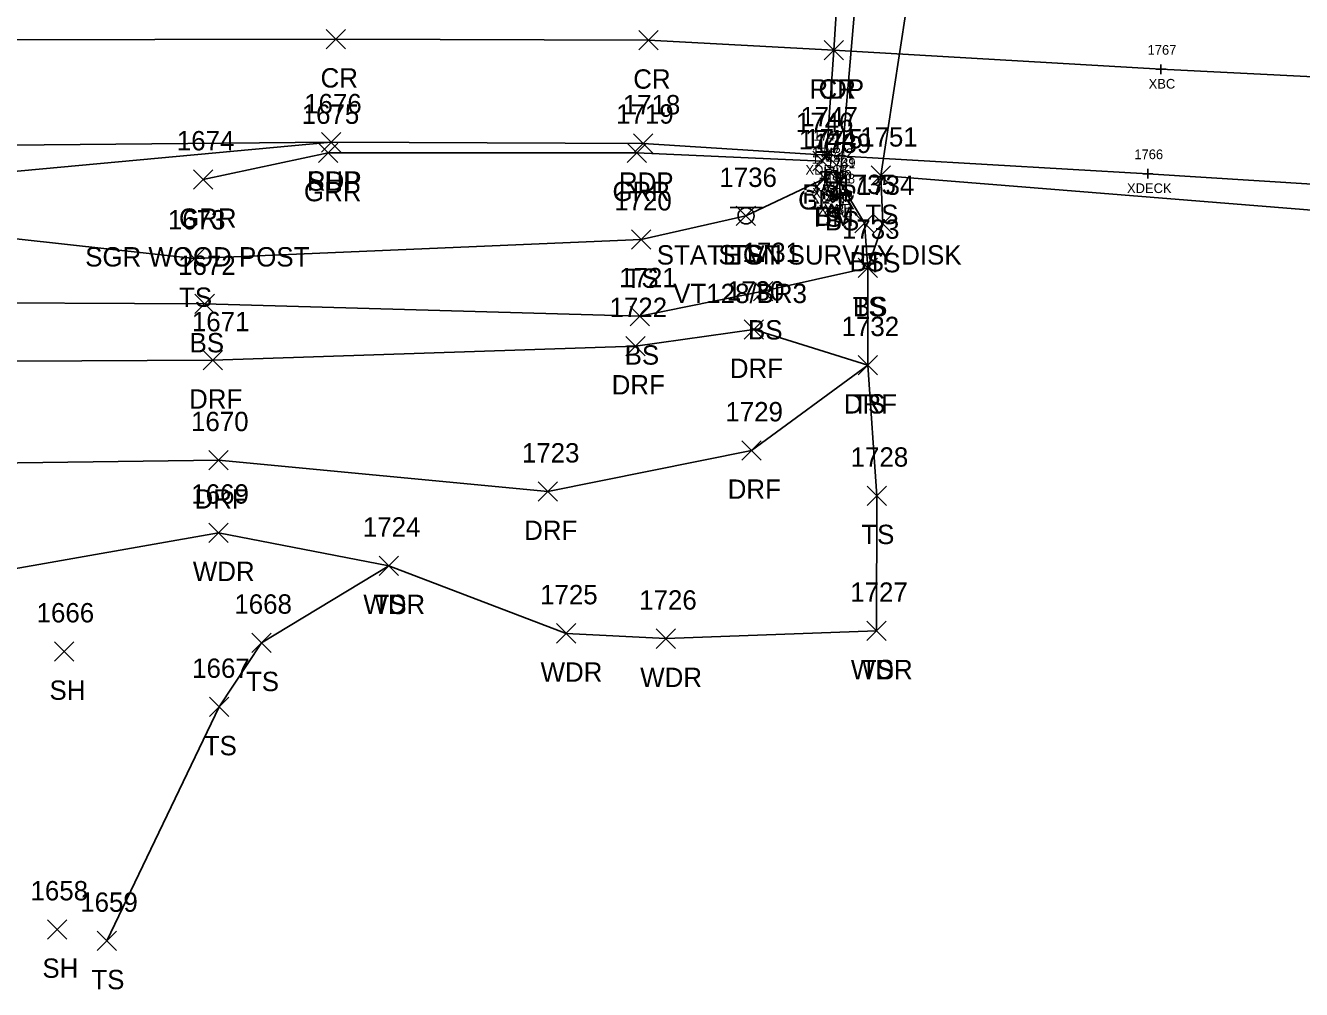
# Model space of a CAD drawing. Extents: x 1497084 to 1499861, y 734741 to 735567.
# Drawn here: x 1499429.7 to 1499561.5, y 735367.2 to 735466.8 of the extents above; entities that cross this region are included whole.
import ezdxf

# ---------------------------------------------------------------- set-up
doc = ezdxf.new("R2010")
doc.units = 0
for name, color, linetype in [('B_A', 7, 'Continuous'), ('B_I', 7, 'Continuous'), ('B_TIC', 7, 'Continuous'), ('BELB', 7, 'Continuous'), ('BSUBM', 7, 'Continuous'), ('C_A', 7, 'Continuous'), ('C_C', 7, 'Continuous'), ('C_I', 7, 'Continuous'), ('CPBM', 7, 'Continuous'), ('L_A', 7, 'Continuous'), ('L_I', 7, 'Continuous'), ('L_TIC', 7, 'Continuous'), ('LAWA', 7, 'Continuous'), ('LELB', 7, 'Continuous'), ('P_A', 7, 'Continuous'), ('P_I', 7, 'Continuous'), ('P_TIC', 7, 'Continuous'), ('PET', 7, 'Continuous'), ('PRC', 7, 'Continuous'), ('PSP', 7, 'Continuous'), ('R_A', 7, 'Continuous'), ('R_C', 7, 'Continuous'), ('R_I', 7, 'Continuous'), ('R_TIC', 7, 'Continuous'), ('RDF', 7, 'Continuous'), ('RGR', 7, 'Continuous'), ('S_A', 7, 'Continuous'), ('S_C', 7, 'Continuous'), ('S_I', 7, 'Continuous'), ('SSGN', 7, 'Continuous')]:
    doc.layers.add(name, color=color, linetype=linetype)

msp = doc.modelspace()

# ---------------------------------------------------------------- linework, layer by layer
at = {"layer": 'B_TIC'}
for p, q in [((1499547.02, 735462.29), (1499547.09, 735462.29)), ((1499512.45, 735453.4), (1499512.52, 735453.4)), ((1499512.28, 735451.02), (1499512.35, 735451.02)), ((1499512.32, 735451.69), (1499512.4, 735451.69)), ((1499513.58, 735451.62), (1499513.66, 735451.62)), ((1499545.67, 735451.5), (1499545.75, 735451.5)), ((1499513.54, 735450.56), (1499513.62, 735450.56)), ((1499513.83, 735450.64), (1499513.91, 735450.64)), ((1499512.92, 735449.28), (1499512.99, 735449.28)), ((1499512.92, 735449.28), (1499512.99, 735449.28)), ((1499513.48, 735449.37), (1499513.56, 735449.37)), ((1499513.78, 735448.99), (1499513.85, 735448.99))]:
    msp.add_line(p, q, dxfattribs=at)
for points in [[(1499547.01, 735461.79), (1499547.01, 735462.79)], [(1499546.51, 735462.29), (1499547.51, 735462.29)], [(1499511.94, 735453.4), (1499512.94, 735453.4)], [(1499512.44, 735452.9), (1499512.44, 735453.9)], [(1499512.32, 735451.19), (1499512.32, 735452.19)], [(1499513.58, 735451.12), (1499513.58, 735452.12)], [(1499511.77, 735451.02), (1499512.77, 735451.02)], [(1499511.82, 735451.69), (1499512.82, 735451.69)], [(1499512.27, 735450.52), (1499512.27, 735451.52)], [(1499513.08, 735451.62), (1499514.08, 735451.62)], [(1499513.54, 735450.06), (1499513.54, 735451.06)], [(1499513.83, 735450.14), (1499513.83, 735451.14)], [(1499545.17, 735451.5), (1499546.17, 735451.5)], [(1499545.67, 735451), (1499545.67, 735452)], [(1499512.91, 735448.78), (1499512.91, 735449.78)], [(1499512.91, 735448.78), (1499512.91, 735449.78)], [(1499513.04, 735450.56), (1499514.04, 735450.56)], [(1499513.33, 735450.64), (1499514.33, 735450.64)], [(1499513.48, 735448.87), (1499513.48, 735449.87)], [(1499513.78, 735448.49), (1499513.78, 735449.49)], [(1499512.41, 735449.28), (1499513.41, 735449.28)], [(1499512.41, 735449.28), (1499513.41, 735449.28)], [(1499512.98, 735449.37), (1499513.98, 735449.37)], [(1499513.28, 735448.99), (1499514.28, 735448.99)]]:
    msp.add_lwpolyline(points, dxfattribs=at)
at = {"layer": 'BELB'}
for points in [[(1499547.01, 735462.29), (1499513.2, 735464.25)], [(1499547.01, 735462.29), (1499571.03, 735461.1), (1499595.43, 735458.81)], [(1499512.44, 735453.4), (1499545.67, 735451.5), (1499568.69, 735450.04), (1499594.85, 735447.92)]]:
    msp.add_lwpolyline(points, dxfattribs=at)
at = {"layer": 'BSUBM'}
for points in [[(1499512.91, 735449.28), (1499513.78, 735448.99), (1499513.83, 735450.64), (1499516.08, 735476.74), (1499515.9, 735479.25), (1499514.54, 735478.58)], [(1499512.91, 735449.28), (1499513.48, 735449.37), (1499513.54, 735450.56), (1499513.58, 735451.62), (1499512.32, 735451.69), (1499512.27, 735451.02)]]:
    msp.add_lwpolyline(points, dxfattribs=at)
at = {"layer": 'CPBM'}
for p, q in [((1499512.44, 735450.61), (1499512.44, 735451.61)), ((1499512.44, 735451.61), (1499513.44, 735451.61)), ((1499512.95, 735451.11), (1499512.95, 735451.11)), ((1499512.95, 735451.11), (1499512.95, 735451.11)), ((1499513.44, 735451.61), (1499513.44, 735450.61)), ((1499513.44, 735450.61), (1499512.44, 735450.61))]:
    msp.add_line(p, q, dxfattribs=at)
at = {"layer": 'L_TIC'}
for points in [[(1499511.27, 735450.02), (1499513.27, 735452.02)], [(1499513.27, 735450.02), (1499511.27, 735452.02)], [(1499517.06, 735450.3), (1499519.06, 735452.3)], [(1499519.06, 735450.3), (1499517.06, 735452.3)], [(1499512.83, 735449.64), (1499514.83, 735451.64)], [(1499514.83, 735449.64), (1499512.83, 735451.64)], [(1499503.12, 735446.13), (1499505.12, 735448.13)], [(1499505.12, 735446.13), (1499503.12, 735448.13)], [(1499515.38, 735445.4), (1499517.38, 735447.4)], [(1499517.38, 735445.4), (1499515.38, 735447.4)], [(1499517.27, 735445.31), (1499519.27, 735447.31)], [(1499519.27, 735445.31), (1499517.27, 735447.31)], [(1499492.29, 735443.7), (1499494.29, 735445.7)], [(1499494.29, 735443.7), (1499492.29, 735445.7)], [(1499446.12, 735441.74), (1499448.12, 735443.74)], [(1499448.12, 735441.74), (1499446.12, 735443.74)], [(1499515.74, 735440.77), (1499517.74, 735442.77)], [(1499517.74, 735440.77), (1499515.74, 735442.77)], [(1499515.74, 735440.77), (1499517.74, 735442.77)], [(1499517.74, 735440.77), (1499515.74, 735442.77)], [(1499504.9, 735438.37), (1499506.9, 735440.37)], [(1499506.9, 735438.37), (1499504.9, 735440.37)], [(1499447.18, 735437.04), (1499449.18, 735439.04)], [(1499449.18, 735437.04), (1499447.18, 735439.04)], [(1499492.15, 735435.77), (1499494.15, 735437.77)], [(1499494.15, 735435.77), (1499492.15, 735437.77)], [(1499515.71, 735430.72), (1499517.71, 735432.72)], [(1499517.71, 735430.72), (1499515.71, 735432.72)], [(1499516.64, 735417.23), (1499518.64, 735419.23)], [(1499518.64, 735417.23), (1499516.64, 735419.23)], [(1499448.6, 735413.41), (1499450.6, 735415.41)], [(1499450.6, 735413.41), (1499448.6, 735415.41)], [(1499466.22, 735410), (1499468.22, 735412)], [(1499468.22, 735410), (1499466.22, 735412)], [(1499466.22, 735410), (1499468.22, 735412)], [(1499468.22, 735410), (1499466.22, 735412)], [(1499484.54, 735403.01), (1499486.54, 735405.01)], [(1499486.54, 735403.01), (1499484.54, 735405.01)], [(1499516.61, 735403.27), (1499518.61, 735405.27)], [(1499518.61, 735403.27), (1499516.61, 735405.27)], [(1499516.61, 735403.27), (1499518.61, 735405.27)], [(1499518.61, 735403.27), (1499516.61, 735405.27)], [(1499453.04, 735402.04), (1499455.04, 735404.04)], [(1499455.04, 735402.04), (1499453.04, 735404.04)], [(1499494.84, 735402.46), (1499496.84, 735404.46)], [(1499496.84, 735402.46), (1499494.84, 735404.46)], [(1499432.66, 735401.14), (1499434.66, 735403.14)], [(1499434.66, 735401.14), (1499432.66, 735403.14)], [(1499448.68, 735395.41), (1499450.68, 735397.41)], [(1499450.68, 735395.41), (1499448.68, 735397.41)], [(1499431.92, 735372.42), (1499433.92, 735374.42)], [(1499433.92, 735372.42), (1499431.92, 735374.42)], [(1499437.06, 735371.24), (1499439.06, 735373.24)], [(1499439.06, 735371.24), (1499437.06, 735373.24)]]:
    msp.add_lwpolyline(points, dxfattribs=at)
at = {"layer": 'LAWA'}
msp.add_lwpolyline([(1499407.4, 735368.39), (1499407.84, 735388.76), (1499418.87, 735408.97), (1499449.6, 735414.41), (1499467.22, 735411), (1499485.54, 735404.01), (1499495.84, 735403.46), (1499517.61, 735404.27)], dxfattribs=at)
at = {"layer": 'LELB'}
for points in [[(1499517.61, 735404.27), (1499517.64, 735418.23), (1499516.71, 735431.72), (1499516.74, 735441.77), (1499518.27, 735446.31), (1499518.06, 735451.3), (1499522, 735476.98), (1499523.7, 735480.99)], [(1499224.87, 735431.1), (1499271.08, 735434.05), (1499322.87, 735437.57), (1499384.48, 735442.03), (1499412.03, 735442.18), (1499420.22, 735445.71), (1499447.12, 735442.74), (1499493.29, 735444.7), (1499504.12, 735447.13), (1499512.27, 735451.02)], [(1499577.62, 735446.54), (1499518.06, 735451.3)], [(1498902.07, 735368.05), (1498907.17, 735371.51), (1498940.32, 735377.55), (1498999.63, 735387.02), (1499017.69, 735389.23), (1499022.6, 735383.12), (1499048.5, 735392.29), (1499056.36, 735395.92), (1499109.05, 735409.57), (1499159.67, 735419.26), (1499225.84, 735428.89), (1499272.31, 735428.88), (1499323.36, 735436.06), (1499376.02, 735439.69), (1499385.74, 735428.35), (1499408.33, 735432.03), (1499419.24, 735438.19), (1499448.18, 735438.04), (1499493.15, 735436.77), (1499505.9, 735439.37), (1499516.74, 735441.77), (1499516.38, 735446.4), (1499513.83, 735450.64)], [(1499438.06, 735372.24), (1499449.68, 735396.41), (1499454.04, 735403.04), (1499467.22, 735411)]]:
    msp.add_lwpolyline(points, dxfattribs=at)
at = {"layer": 'P_TIC'}
for points in [[(1499460.73, 735464.4), (1499462.73, 735466.4)], [(1499462.73, 735464.4), (1499460.73, 735466.4)], [(1499493.05, 735464.28), (1499495.05, 735466.28)], [(1499495.05, 735464.28), (1499493.05, 735466.28)], [(1499512.2, 735463.25), (1499514.2, 735465.25)], [(1499514.2, 735463.25), (1499512.2, 735465.25)], [(1499512.2, 735463.25), (1499514.2, 735465.25)], [(1499514.2, 735463.25), (1499512.2, 735465.25)], [(1499460.26, 735453.74), (1499462.26, 735455.74)], [(1499462.26, 735453.74), (1499460.26, 735455.74)], [(1499460.26, 735453.74), (1499462.26, 735455.74)], [(1499462.26, 735453.74), (1499460.26, 735455.74)], [(1499492.51, 735453.63), (1499494.51, 735455.63)], [(1499494.51, 735453.63), (1499492.51, 735455.63)], [(1499511.44, 735452.4), (1499513.44, 735454.4)], [(1499513.44, 735452.4), (1499511.44, 735454.4)]]:
    msp.add_lwpolyline(points, dxfattribs=at)
at = {"layer": 'PET'}
msp.add_lwpolyline([(1498842.44, 735373.21), (1498892.67, 735381.87), (1498940.26, 735389.17), (1498997.67, 735398.94), (1499056.44, 735408.41), (1499108.2, 735417.59), (1499160.18, 735425.34), (1499224.61, 735435.78), (1499269.11, 735441.52), (1499319.5, 735447.91), (1499378.39, 735452.04), (1499424.16, 735454.42), (1499461.26, 735454.74), (1499493.51, 735454.63), (1499512.44, 735453.4), (1499513.2, 735464.25), (1499513.91, 735475.18)], dxfattribs=at)
at = {"layer": 'PRC'}
msp.add_lwpolyline([(1498839.89, 735384.37), (1498890.74, 735392.79), (1498939.31, 735400.24), (1498995.85, 735410.01), (1499056.08, 735419.64), (1499106.34, 735428.63), (1499159.02, 735436.58), (1499221.74, 735447.44), (1499267.15, 735453.23), (1499318.55, 735459.5), (1499378.61, 735463.51), (1499424.29, 735465.34), (1499461.73, 735465.4), (1499494.05, 735465.28), (1499513.2, 735464.25)], dxfattribs=at)
at = {"layer": 'PSP'}
msp.add_lwpolyline([(1498843.61, 735368.57), (1498860.46, 735371.23), (1498865.28, 735372.42), (1498905.37, 735378.8), (1498940.19, 735384.06), (1498998.48, 735394.31), (1499018.85, 735397.58), (1499054.41, 735403.83), (1499108.72, 735412.03), (1499160.14, 735420.81), (1499224.87, 735431.1), (1499270.68, 735437.25), (1499320.13, 735443.34), (1499381.94, 735448.71), (1499417.25, 735450.68), (1499461.26, 735454.74)], dxfattribs=at)
at = {"layer": 'R_TIC'}
for points in [[(1499459.95, 735452.65), (1499461.95, 735454.65)], [(1499461.95, 735452.65), (1499459.95, 735454.65)], [(1499491.84, 735452.67), (1499493.84, 735454.67)], [(1499493.84, 735452.67), (1499491.84, 735454.67)], [(1499511.03, 735451.81), (1499513.03, 735453.81)], [(1499513.03, 735451.81), (1499511.03, 735453.81)], [(1499447.04, 735449.91), (1499449.04, 735451.91)], [(1499449.04, 735449.91), (1499447.04, 735451.91)], [(1499503.93, 735434.39), (1499505.93, 735436.39)], [(1499505.93, 735434.39), (1499503.93, 735436.39)], [(1499491.72, 735432.69), (1499493.72, 735434.69)], [(1499493.72, 735432.69), (1499491.72, 735434.69)], [(1499448.04, 735431.22), (1499450.04, 735433.22)], [(1499450.04, 735431.22), (1499448.04, 735433.22)], [(1499515.71, 735430.72), (1499517.71, 735432.72)], [(1499517.71, 735430.72), (1499515.71, 735432.72)], [(1499515.71, 735430.72), (1499517.71, 735432.72)], [(1499517.71, 735430.72), (1499515.71, 735432.72)], [(1499503.7, 735421.91), (1499505.7, 735423.91)], [(1499505.7, 735421.91), (1499503.7, 735423.91)], [(1499448.6, 735420.9), (1499450.6, 735422.9)], [(1499450.6, 735420.9), (1499448.6, 735422.9)], [(1499482.66, 735417.66), (1499484.66, 735419.66)], [(1499484.66, 735417.66), (1499482.66, 735419.66)]]:
    msp.add_lwpolyline(points, dxfattribs=at)
at = {"layer": 'RDF'}
for points in [[(1499408.33, 735432.03), (1499449.04, 735432.22), (1499492.72, 735433.69), (1499504.93, 735435.39), (1499516.71, 735431.72)], [(1499405.49, 735421.31), (1499449.6, 735421.9), (1499483.66, 735418.66), (1499504.7, 735422.91), (1499516.71, 735431.72)]]:
    msp.add_lwpolyline(points, dxfattribs=at)
at = {"layer": 'RGR'}
msp.add_lwpolyline([(1499448.04, 735450.91), (1499460.95, 735453.65), (1499492.84, 735453.67), (1499512.03, 735452.81)], dxfattribs=at)
at = {"layer": 'SSGN'}
for p, q in [((1499502.5, 735447.99), (1499505.83, 735447.99)), ((1499504.14, 735447.15), (1499504.14, 735447.15))]:
    msp.add_line(p, q, dxfattribs=at)
msp.add_circle((1499504.14, 735447.15), 0.833, dxfattribs=at)

# ---------------------------------------------------------------- texts
at = {"layer": 'B_A'}
for s, p in [('XBC', (1499545.75, 735460.29)), ('XDECK', (1499510.28, 735451.4)), ('XAT', (1499511.02, 735449.69)), ('XAT', (1499510.98, 735449.02)), ('XAT', (1499512.24, 735448.56)), ('XAT', (1499512.28, 735449.62)), ('XAB', (1499512.55, 735448.64)), ('XDECK', (1499543.51, 735449.5)), ('XAT', (1499511.62, 735447.28)), ('XAB', (1499511.63, 735447.28)), ('XAT', (1499512.18, 735447.37)), ('XAB', (1499512.5, 735446.99))]:
    msp.add_text(s, height=1, dxfattribs=at).set_placement(p)
at = {"layer": 'B_I'}
for s, p in [('1767', (1499545.64, 735463.79)), ('1747', (1499511.1, 735454.9)), ('1744', (1499510.93, 735452.52)), ('1743', (1499510.97, 735453.19)), ('1742', (1499512.23, 735453.12)), ('1766', (1499544.27, 735453)), ('1739', (1499512.48, 735452.14)), ('1741', (1499512.47, 735452.06)), ('1737', (1499511.57, 735450.78)), ('1737', (1499511.57, 735450.78)), ('1740', (1499512.09, 735450.87)), ('1738', (1499512.43, 735450.49))]:
    msp.add_text(s, height=1, dxfattribs=at).set_placement(p)
at = {"layer": 'C_A'}
msp.add_text('BM', height=2, dxfattribs=at).set_placement((1499511.26, 735446.11))
at = {"layer": 'C_C'}
msp.add_text('STATE VT SURVEY DISK', height=2, dxfattribs=at).set_placement((1499494.91, 735442.11))
at = {"layer": 'C_I'}
msp.add_text('1745', height=2, dxfattribs=at).set_placement((1499510.25, 735454.11))
at = {"layer": 'L_A'}
for s, p in [('TS', (1499516.47, 735446.3)), ('TS', (1499510.68, 735446.02)), ('BS', (1499512.27, 735445.64)), ('TS', (1499502.53, 735442.13)), ('BS', (1499514.82, 735441.4)), ('TS', (1499516.68, 735441.31)), ('TS', (1499491.69, 735439.7)), ('TS', (1499445.53, 735437.74)), ('TS', (1499515.15, 735436.77)), ('BS', (1499515.18, 735436.77)), ('BS', (1499504.34, 735434.37)), ('BS', (1499446.62, 735433.04)), ('BS', (1499491.59, 735431.77)), ('TS', (1499515.11, 735426.72)), ('TS', (1499516.05, 735413.23)), ('WDR', (1499446.96, 735409.41)), ('WDR', (1499464.58, 735406)), ('TS', (1499465.63, 735406)), ('WDR', (1499482.9, 735399.01)), ('WDR', (1499514.97, 735399.27)), ('TS', (1499516.01, 735399.27)), ('TS', (1499452.45, 735398.04)), ('WDR', (1499493.2, 735398.46)), ('SH', (1499432.14, 735397.14)), ('TS', (1499448.09, 735391.41)), ('SH', (1499431.41, 735368.42)), ('TS', (1499436.47, 735367.24))]:
    msp.add_text(s, height=2, dxfattribs=at).set_placement(p)
at = {"layer": 'L_I'}
for s, p in [('1744', (1499509.58, 735454.02)), ('1751', (1499515.93, 735454.3)), ('1739', (1499511.13, 735453.64)), ('1736', (1499501.38, 735450.13)), ('1735', (1499513.68, 735449.4)), ('1734', (1499515.58, 735449.31)), ('1720', (1499490.51, 735447.7)), ('1673', (1499444.38, 735445.74)), ('1733', (1499514.05, 735444.77)), ('1733', (1499514.05, 735444.77)), ('1731', (1499503.77, 735442.37)), ('1672', (1499445.44, 735441.04)), ('1721', (1499491.02, 735439.77)), ('1732', (1499514.01, 735434.72)), ('1728', (1499514.95, 735421.23)), ('1669', (1499446.8, 735417.41)), ('1724', (1499464.53, 735414)), ('1724', (1499464.53, 735414)), ('1725', (1499482.85, 735407.01)), ('1726', (1499493.09, 735406.46)), ('1727', (1499514.91, 735407.27)), ('1727', (1499514.91, 735407.27)), ('1666', (1499430.81, 735405.14)), ('1668', (1499451.25, 735406.04)), ('1667', (1499446.89, 735399.41)), ('1658', (1499430.18, 735376.42)), ('1659', (1499435.32, 735375.24))]:
    msp.add_text(s, height=2, dxfattribs=at).set_placement(p)
at = {"layer": 'P_A'}
for s, p in [('CR', (1499460.16, 735460.4)), ('CR', (1499492.48, 735460.28)), ('RDP', (1499510.69, 735459.25)), ('CR', (1499511.63, 735459.25)), ('SHP', (1499458.79, 735449.74)), ('RDP', (1499458.75, 735449.74)), ('RDP', (1499491, 735449.63)), ('RDP', (1499509.93, 735448.4))]:
    msp.add_text(s, height=2, dxfattribs=at).set_placement(p)
at = {"layer": 'P_I'}
for s, p in [('1676', (1499458.46, 735457.74)), ('1676', (1499458.46, 735457.74)), ('1718', (1499491.39, 735457.63)), ('1747', (1499509.75, 735456.4))]:
    msp.add_text(s, height=2, dxfattribs=at).set_placement(p)
at = {"layer": 'R_A'}
for s, p in [('GRR', (1499490.33, 735448.67)), ('GRR', (1499458.44, 735448.65)), ('GRR', (1499509.52, 735447.81)), ('GRR', (1499445.53, 735445.91)), ('DRF', (1499502.46, 735430.39)), ('DRF', (1499490.25, 735428.69)), ('DRF', (1499446.57, 735427.22)), ('DRF', (1499514.24, 735426.72)), ('DRF', (1499514.24, 735426.72)), ('DRF', (1499502.24, 735417.91)), ('DRF', (1499447.13, 735416.9)), ('DRF', (1499481.2, 735413.66))]:
    msp.add_text(s, height=2, dxfattribs=at).set_placement(p)
at = {"layer": 'R_C'}
msp.add_text('SGR WOOD POST', height=2, dxfattribs=at).set_placement((1499435.83, 735441.91))
at = {"layer": 'R_I'}
for s, p in [('1675', (1499458.21, 735456.65)), ('1719', (1499490.71, 735456.67)), ('1746', (1499509.28, 735455.81)), ('1674', (1499445.3, 735453.91)), ('1730', (1499502.15, 735438.39)), ('1722', (1499490.03, 735436.69)), ('1671', (1499446.86, 735435.22)), ('1732', (1499514.01, 735434.72)), ('1732', (1499514.01, 735434.72)), ('1729', (1499502, 735425.91)), ('1670', (1499446.77, 735424.9)), ('1723', (1499480.97, 735421.66))]:
    msp.add_text(s, height=2, dxfattribs=at).set_placement(p)
at = {"layer": 'S_A'}
msp.add_text('SIGN', height=2, dxfattribs=at).set_placement((1499501.28, 735442.13))
at = {"layer": 'S_C'}
msp.add_text('VT128/BR3', height=2, dxfattribs=at).set_placement((1499496.61, 735438.13))
at = {"layer": 'S_I'}
msp.add_text('1736', height=2, dxfattribs=at).set_placement((1499501.38, 735450.13))

doc.saveas('drawing.dxf')
